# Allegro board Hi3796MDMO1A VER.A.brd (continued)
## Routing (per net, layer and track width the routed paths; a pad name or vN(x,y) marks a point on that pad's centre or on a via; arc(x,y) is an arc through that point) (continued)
STANDBY_PWROFF: length 225
  TOP w0.127: 36.96,68.45 37.54,67.87 45.59,67.87 46.86,69.14 v1(46.86,71.37) ; 36.96,68.45 36.42,67.92 24.23,67.92 23.37,67.06 18.36,67.06 12.19,60.88 12.19,57.58 13.84,55.93 v1(15.27,55.93) ; 36.96,68.45 R163.1 ; U10.AG27 v2(72.38,42.74) ; v1(35.31,13.84) 50.88,13.84 v1(53.34,16.31) 55.85,13.79 64.29,13.79 67.08,16.59 68.5,16.59 73.79,21.87 v1(73.79,28.83) ; v1(103.14,52.05) 101.96,53.24 101.96,55.78 100.91,56.82 100.91,57.33 100.46,57.79 99.67,57.79 R73.1
  BOTTOM w0.127: v1(103.14,52.05) 101.71,52.05 91.44,41.78 88.52,41.78 82.68,35.94 78.13,35.94 76.71,34.52 76.71,31.75 v1(73.79,28.83) R142.1 72.03,32.87 71.75,33.15 71.75,41.4 71.53,41.63 R88.1 71.92,42.22 71.92,42.28 v2(72.38,42.74) ; v1(35.31,13.84) 32.38,16.76 21.21,16.76 14.1,23.88 14.1,33.53 15.37,34.8 15.37,39.24 16,39.88 16,55.19 v1(15.27,55.93) ; v1(53.34,16.31) 53.37,16.33 R33.1 ; R30.1 47.09,71.6 v1(46.86,71.37)
TSI0_CLK: length 96.6
  TOP w0.127: J7.19 130.58,79.63 132.33,79.63 134.87,77.09 134.87,56.64 131.7,53.47 119,53.47 117.64,54.83 111.47,54.83 108.84,52.2 106.3,52.2 104.09,49.99 91.36,49.99 89.28,52.07 82.98,52.07 80.57,54.48 75.6,54.48 75.3,54.18 73.23,54.18 73.03,53.98 72.36,53.98 72,54.34 U10.N27
TSI0_D0: length 90.8
  TOP w0.127: U10.N28 73.18,54.74 73.79,54.74 74.3,55.25 81.29,55.25 83.76,52.77 90.03,52.77 91.82,50.98 103.63,50.98 105.89,53.24 108.86,53.24 111.43,55.8 119.2,55.8 120.27,54.74 131.19,54.74 133.86,57.4 133.86,75.82 132.33,77.34 130.32,77.34 J7.17
TSI0_VALID: length 98.1
  TOP w0.127: J7.21 128.14,82.28 128.14,77.85 129.03,76.96 132.21,76.96 133.48,75.69 133.48,57.53 130.94,54.99 120.37,54.99 119.31,56.06 111.22,56.06 108.73,53.57 105.84,53.57 103.58,51.31 91.87,51.31 90.16,53.02 83.87,53.02 81.39,55.5 74.04,55.5 73.68,55.14 U10.M26
TSI1_CLK: length 14.4
  TOP w0.127: R10.1 79.17,64.82 78.61,64.26 78.61,62.87 75.67,59.92 75.67,58.19 74.75,57.28 73.32,57.28 U10.K28
TSI1_D0: length 12.2
  TOP w0.127: R13.1 79.6,62.43 76.63,59.46 76.63,58.14 74.78,56.29 72.36,56.29 72.02,55.94 U10.L27
TSI1_SYNC: length 17.4
  TOP w0.127: U10.H26 74.03,58.34 74.42,58.72 74.42,61.47 74.46,61.51 74.46,61.51 75.28,62.33 76.05,62.33 77.47,63.75 77.47,65.91 78.64,67.08 80.42,67.08 80.64,66.85 R226.1
TSI1_VALID: length 17
  TOP w0.127: v1(79.63,66.55) 78.61,66.55 77.85,65.79 77.85,63.5 76.2,61.85 75.15,61.85 74.68,61.37 74.68,58.6 74.12,58.04 72.48,58.04 U10.J27
  TOP w0.381: R5.1 v1(81.28,65.84)
  BOTTOM w0.127: v1(79.63,66.55) 80.34,65.84 v1(81.28,65.84)
TX+_PHY0: length 38.4
  TOP w0.114: R80.1 33.3,83.69 34.29,83.69 35.56,82.42 39.88,82.42 40.5,83.05 41.29,83.05 41.4,82.93 U27.8 U27.1 43.18,82.93 43.3,83.06 44.76,83.06 45.95,81.87 51.55,76.27 51.55,66.49 53.71,64.33 53.71,63.95 53.96,63.69 53.96,61.95 U10.D5
TX-_PHY0: length 38.5
  TOP w0.114: R79.1 33.29,83.96 34.4,83.96 35.67,82.69 39.77,82.69 40.39,83.31 41.27,83.31 41.4,83.44 U27.7 U27.2 43.15,83.44 43.27,83.32 44.87,83.32 46.14,82.06 51.82,76.38 51.82,66.6 52.34,66.07 52.51,66.07 52.54,66.1 52.7,66.1 52.86,65.94 52.86,65.78 52.83,65.75 52.83,65.59 52.99,65.42 53.15,65.42 53.18,65.45 53.34,65.45 53.51,65.29 53.51,65.13 53.48,65.1 53.48,64.94 53.98,64.44 53.98,64.06 54.23,63.8 54.23,62.48 U10.C5
UART0_RXD: length 53.2
  TOP w0.127: v1(86.49,26.09) 86,26.09 79.25,32.84 79.25,33.78 74.78,38.25 74.78,42.49 73.33,43.94 U10.AF28 ; J18.2 66.95,12.09 67.94,13.08 R136.1 68.55,13.69 71.37,16.51 80.64,16.51 83.82,19.69 v1(83.82,20.07)
  BOTTOM w0.127: v1(86.49,26.09) 86.41,26.09 83.82,23.49 v1(83.82,20.07)
UART0_TXD: length 41.9
  TOP w0.127: v1(74.93,28.83) 74.24,28.14 74.24,21.67 68.58,16 67.51,16 67.31,15.8 67.31,13.84 67.16,13.69 R135.2 66.67,13.21 65.7,12.23 J18.3 ; U10.AF27 72.35,43.56 73.33,43.56 74.42,42.47 74.42,37.72 v1(77.85,34.29)
  BOTTOM w0.127: v1(77.85,34.29) 77.57,34.01 77.57,31.47 v1(74.93,28.83)
USB0_DM: length 58.1
  TOP w0.152: J6.2 9.98,66.38 12.38,66.38 D5.1 C341.2 14.05,66.37 14.68,66.37 17.21,68.9 21.4,68.9 v1(21.72,69.21) ; v1(56.22,69.24) 55.91,68.92 55.91,66.95 56.59,66.27 56.59,65.94 56.39,65.74 56.39,65.28 56.59,65.07 56.59,64.72 56.39,64.52 56.39,64.14 56.6,63.94 U10.A8
  BOTTOM w0.152: v1(21.72,69.21) 22.06,68.87 23.68,68.87 24.07,68.48 29.2,68.48 32.04,71.32 45.14,71.32 46.15,70.31 49.14,70.31 49.77,70.94 54.97,70.94 55.91,69.99 55.91,69.54 v1(56.22,69.24)
USB0_DP: length 58.1
  TOP w0.152: v1(55.29,69.24) 55.58,68.95 55.58,66.82 56.06,66.33 56.06,64.01 56.78,63.29 U10.B8 ; v1(21.72,68.28) 21.56,68.43 21.56,68.44 21.44,68.57 17.35,68.57 14.82,66.04 14.02,66.04 C342.2 D4.1 12.38,66.05 10.19,66.05 J6.3
  BOTTOM w0.152: v1(55.29,69.24) 55.58,69.53 55.58,69.86 54.83,70.61 49.91,70.61 49.28,69.98 46.01,69.98 45,70.99 32.18,70.99 29.34,68.15 23.93,68.15 23.55,68.54 21.98,68.54 v1(21.72,68.28)
USB01_1V1: length 4.3
  TOP w0.254: U10.H11 v2(58.78,58.74)
  BOTTOM w0.381: LB31.2 58.69,57.76 58.64,57.71 C336.1 C334.1 58.76,58.72 v2(58.78,58.74)
USB01_3V3: length 3.9
  TOP w0.254: U10.E10 v2(57.98,61.14)
  BOTTOM w0.381: v2(57.98,61.14) 58.62,61.78 C182.1 C10.1 59.77,62 60.36,62.6 LB20.2
USB1_DM: length 67.1
  TOP w0.152: v1(58.89,70.38) 58.59,70.08 58.59,65.57 58.35,65.34 58.35,65.01 58.09,64.74 57.76,64.74 57.48,64.47 57.48,64.19 57.68,63.98 57.68,63.65 57.48,63.45 57.48,62.43 U10.C9 ; J9.2 10.13,88.23 11.87,88.23 D10.1 C343.2 13.92,88.57 v1(14.02,88.47)
  BOTTOM w0.152: v1(58.89,70.38) 58.6,70.67 58.6,71.38 56.61,73.37 49.73,80.26 42.05,80.26 40.47,81.84 25.35,81.84 19,88.19 14.3,88.19 v1(14.02,88.47)
USB1_DP: length 67.2
  TOP w0.152: J9.3 10.03,87.9 11.77,87.9 D15.1 C344.2 13.94,87.45 v1(14.02,87.53) ; U10.D9 57.15,61.96 57.15,64.6 58.25,65.71 58.25,70.08 v1(57.95,70.38)
  BOTTOM w0.152: v1(57.95,70.38) 58.27,70.7 58.27,71.25 56.38,73.14 49.59,79.93 41.91,79.93 40.34,81.51 25.21,81.51 18.86,87.86 14.35,87.86 v1(14.02,87.53)
USB01_VBUS: length 0.9
  TOP w0.508: C49.1 12.95,68.58
  vias: v1(11.68,91.82) v1(11.68,90.68) v1(11.7,73.8) v1(11.7,72.66) v1(12.73,73.8)
USB2_DM: length 45.7
  TOP w0.152: U10.T27 72.35,51.56 73.06,51.56 73.14,51.64 80.1,51.64 81.98,49.76 87.62,49.76 90.67,46.71 104.84,46.71 106,47.88 111.25,47.88 111.53,47.6 112.17,47.6 113.01,46.75 U7.4
USB2_DP: length 45.7
  TOP w0.152: U7.3 113.13,48.75 112.3,47.93 111.67,47.93 111.39,48.21 105.87,48.21 104.7,47.04 90.81,47.04 87.76,50.09 82.12,50.09 80.06,52.15 79.76,52.15 79.58,51.97 79.15,51.97 78.92,52.2 78.62,52.2 78.39,51.97 77.96,51.97 77.73,52.2 77.4,52.2 77.17,51.97 76.74,51.97 76.57,52.15 76.13,52.15 75.96,51.97 75.27,51.97 75.12,52.12 74.66,52.12 74.51,51.97 74.05,51.97 73.9,52.12 73.44,52.12 73.29,51.97 73,51.97 72.92,51.89 72.82,51.89 U10.T28
USB2_RBI: length 2.6
  TOP w0.127: U10.R25 v2(70.78,52.34)
  BOTTOM w0.127: R85.1 R43.1 71.02,52.58 v2(70.78,52.34)
USB3_DM: length 86.1
  TOP w0.152: U10.AH19 65.53,42.29 65.53,41.11 65.13,40.71 65.13,40.43 65.28,40.27 65.41,40.27 65.56,40.12 65.56,39.82 65.41,39.66 65.28,39.66 65.13,39.51 65.13,39.21 65.28,39.06 65.41,39.06 65.56,38.9 65.56,38.6 65.41,38.45 65.28,38.45 65.13,38.29 65.13,38.03 54.24,27.15 31.68,27.15 25.73,33.11 25.73,39.55 15.32,49.96 10.97,49.96 8.64,47.62 8.64,46.88 8.84,46.68 8.84,46.3 8.64,46.1 8.64,45.82 8.86,45.59 8.86,45.31 8.64,45.09 8.64,44.48 8.94,44.17 9.09,44.17 J12.2
USB3_DP: length 86.1
  TOP w0.152: J12.3 9.3,43.84 8.8,43.84 8.31,44.34 8.31,47.76 10.83,50.29 15.46,50.29 26.06,39.69 26.06,33.24 31.82,27.48 54.11,27.48 64.8,38.17 64.8,40.84 65.2,41.25 65.2,42.76 U10.AG19
USB3_REXT: length 2.4
  TOP w0.127: U10.AD18 v2(65.18,45.14)
  BOTTOM w0.127: R55.1 66.18,44.78 66.14,44.74 65.57,44.74 v2(65.18,45.14)
USB3_RXN: length 77.9
  TOP w0.152: U10.AG21 67.56,42.75 67.56,42.42 68,41.98 68,37.75 54.91,24.66 31.01,24.66 23.47,32.21 23.47,37.58 20.11,40.94 12.36,40.94 J12.5
USB3_RXP: length 77.8
  TOP w0.152: J12.6 12.37,41.27 13.51,41.27 13.77,41.53 14.12,41.53 14.38,41.27 14.73,41.27 14.98,41.53 15.34,41.53 15.59,41.27 15.95,41.27 16.2,41.53 16.56,41.53 16.81,41.27 17.17,41.27 17.42,41.53 17.78,41.53 18.03,41.27 20.24,41.27 23.8,37.72 23.8,32.34 31.15,24.99 54.77,24.99 67.67,37.89 67.67,38.23 67.41,38.48 67.41,38.84 67.67,39.09 67.67,39.44 67.41,39.7 67.41,40.05 67.67,40.31 67.67,40.66 67.41,40.92 67.41,41.27 67.67,41.53 67.67,41.85 U10.AH21
USB3_TXN: length 75.5
  TOP w0.152: C129.2 16.03,46.99 16.38,46.99 24.58,38.79 24.58,32.63 26.46,30.75 31.36,25.85 54.56,25.85 66.75,38.04 66.75,44.36 U10.AE20
USB3_TXP: length 75.6
  TOP w0.152: C70.2 15.95,47.32 16.52,47.32 17.11,46.73 17.38,46.73 17.68,46.43 17.68,46.22 17.68,46.16 17.97,45.87 18.24,45.87 18.54,45.57 18.54,45.36 18.54,45.3 24.91,38.93 24.91,32.77 31.5,26.18 32.09,26.18 32.25,26.34 32.7,26.34 32.86,26.18 33.31,26.18 33.47,26.34 33.92,26.34 34.08,26.18 52.11,26.18 52.29,26.37 52.72,26.37 52.9,26.18 53.33,26.18 53.51,26.37 53.94,26.37 54.12,26.18 54.42,26.18 66.42,38.18 66.42,39.34 66.27,39.5 66.27,39.9 66.42,40.06 66.42,40.46 66.27,40.61 66.27,41.09 66.42,41.24 66.42,41.52 66.24,41.7 66.24,42.09 66.42,42.27 66.42,42.55 66.19,42.77 66.19,43.08 66.42,43.31 66.42,43.98 U10.AF20
USB_BOOT: length 11.3
  TOP w0.127: v1(75.18,70.1) 73.03,67.94 73.03,65.61 71.98,64.56 U10.A27
  BOTTOM w0.127: R40.2 76.71,71.63 v1(75.18,70.1)
USBRBIAS: length 2.2
  TOP w0.254: U10.G11 v2(58.78,59.54)
  BOTTOM w0.254: v2(58.78,59.54) 58.83,59.49 R87.2 R44.2
VDAC_3V3: length 1.1
  TOP w0.254: U10.F24 v2(69.98,60.34) ; U10.F23 v2(69.18,60.34)
VDAC_IREF: length 1.2
  TOP w0.127: U10.B24 v2(69.98,63.54)
  BOTTOM w0.127: R32.2 69.94,63.58 v2(69.98,63.54)
XIN: length 14.3
  TOP w0.203: X2.1 82.64,41.11 82.4,41.35 78.51,41.35 78.33,41.17 C364.1 77.7,40.82 R1.2 77.11,41.3 75.98,42.43 75.98,42.89 73.86,45.01 72.5,45.01 U10.AD27
XOUT: length 7.1
  TOP w0.203: R14.1 77.8,42.09 77.77,42.11 R1.1 76.43,42.9 76.43,43.13 74.02,45.54 U10.AD28
$4N759:
  vias: v1(22.48,98.81) v1(22.48,97.66) v1(23.62,98.81) v1(23.62,97.66)
$4N770: length 30.1
  TOP w0.127: R7.2 C43.1 101.37,53.61 v1(101.36,53.59)
  BOTTOM w0.127: R21.1 76.87,61.79 C71.1 78.85,61.79 85.85,54.79 95.96,54.79 97.03,53.72 101.23,53.72 v1(101.36,53.59)
$4N771: length 4.5
  TOP w0.381: U11.6 97.71,56.39 R99.2 R70.1 R53.1 C76.1
$4N777: length 1.1
  TOP w0.381: R7.1 R70.2
$4N778: length 2.6
  TOP w0.381: U11.1 97.9,58.6 C8.1 R73.2
$4N808: length 46.7
  TOP w0.127: v1(73.79,30.15) 73.15,29.51 73.15,27.05 72.77,26.67 71.88,26.67 71.6,26.39 C45.1 R49.2
  BOTTOM w0.127: C72.1 74.99,64.22 75.08,64.14 R23.1 75.72,62.92 75.72,61.44 77.09,60.07 78.36,60.07 80.01,58.42 80.01,45.67 78.28,43.94 78.28,42.88 74.93,39.52 74.93,31.29 v1(73.79,30.15)
$4N809: length 1
  TOP w0.381: R49.1 R17.2
$4N813: length 4
  TOP w0.381: v1(71.09,26.88) 70.57,26.88 70.14,26.45 U13.1
  BOTTOM w0.508: R142.2 C5.1 71.22,27 v1(71.09,26.88)
$4N877: length 3.9
  TOP w0.508: U15.5 34.92,70.91 R52.1 C84.1 R120.1
$4N879: length 3.4
  TOP w0.508: C30.1 R163.2 R6.2 37.97,71.42 U15.1
$4N1045: length 1.8
  TOP w0.508: U18.5 R95.2
$4N1055: length 8.2
  TOP w0.508: C178.2 29.84,71.75 29.59,72.01 v1(29.59,72.39)
  BOTTOM w0.508: v1(29.59,72.39) 29.59,73.05 30.48,73.94 30.48,75.95 29.84,76.58 v1(27.81,76.58)
$4N1066: length 1.8
  TOP w0.508: U18.6 28.64,71.39 R190.1
$4N1068: length 1
  TOP w0.508: R190.2 C178.1
$4N1073: length 1.8
  TOP w0.508: R172.1 26.67,71.88 26.74,71.95 U18.4
$4N1075: length 2.6
  TOP w0.508: R191.1 R105.1 25.45,70.38 R172.2
$4N1116: length 3.8
  TOP w0.381: U1.5 61.71,16.64 R131.1 C112.1 R100.1
$4N1127: length 2.5
  TOP w0.381: R48.2 C24.1 61.22,18.54 U1.1
$4N1138: length 5.3
  TOP w0.508: R47.1 71.58,22.99 71.58,22.43 70.99,21.84 70.99,20.45 ; R47.1 70.87,22.99 70.67,23.18 U13.6 ; R47.1 71.58,23.98 R17.1
$5N541: length 3.3
  TOP w0.508: Q4.3 52.07,20.62 v1(52.96,20.62)
  BOTTOM w0.508: v1(52.96,20.62) 52.55,20.22 R144.2 R118.2
$5N542: length 15
  TOP w0.381: v1(49.02,16.56) 48.39,16.56 Q8.1
  BOTTOM w0.381: R118.1 53.37,18.19 53.07,17.89 52.08,17.89 51.45,18.53 C6.2 51.05,17.65 49.96,16.56 v1(49.02,16.56) 49.02,18.21 48.03,19.2 46.71,19.2 46.1,19.81 Q13.1
$5N591: length 4.7
  TOP w0.508: Q3.1 45.85,76.5 v1(44.96,75.62)
  BOTTOM w0.508: C133.2 44.69,75.88 v1(44.96,75.62) 44.98,75.59 R75.1
$5N592: length 4.1
  TOP w0.508: v1(46.1,72.06) 46.61,72.57 Q9.3
  BOTTOM w0.508: R75.2 46.2,74.5 R98.2 46.1,73.56 v1(46.1,72.06)
$5N601: length 3.2
  TOP w0.508: Q4.1 50.93,16.81 v1(51.05,16.69)
  BOTTOM w0.508: R33.2 51.38,17.02 v1(51.05,16.69)
$5N603: length 2.3
  TOP w0.508: v1(48.26,71.3) 48.51,71.55 Q9.1
  BOTTOM w0.508: R30.2 47.9,71.65 v1(48.26,71.3)
$6N188: length 3.1
  TOP w0.203: X2.3 80.13,42.48 79.5,43.1 C365.1 R14.2
$6N2484: length 6.3
  TOP w0.127: R16.2 47.88,64.64 47.88,63.81 50.95,60.74 U10.E1
$7N2063: length 13.9
  BOTTOM w0.127: R40.1 C146.1 77.85,74.68 78.18,75 S10.1 79.45,76.78 80.39,77.72 80.39,82.68 80.08,82.98 S10.2
$8N1731: length 1.3
  TOP w0.127: U10.AC17 v2(64.38,45.94)
  BOTTOM w0.127: v2(64.38,45.94) 64.39,45.92 R45.1
$8N1816: length 5.7
  TOP w0.114: R36.2 56.37,39.25 56.71,39.58 56.71,40.89 56.38,41.22 56.38,43.32 56.78,43.73 56.78,43.93 U10.AF8
$8N1817: length 5.2
  TOP w0.114: U10.AG8 56.64,43 56.64,42.53 56.85,42.33 56.85,42.05 56.64,41.84 56.64,41.33 56.97,41 56.97,39.47 56.52,39.02 R37.2
$11N894: length 2.2
  TOP w0.127: U3.L8 v2(36.59,55.84)
  BOTTOM w0.127: R46.2 36.19,57.3 36.19,56.48 36.32,56.35 36.41,56.26 36.59,56.08 v2(36.59,55.84)
$12N1176: length 1.2
  TOP w0.127: U6.L8 v2(37.39,39.43)
  BOTTOM w0.127: R71.2 37.39,39.98 v2(37.39,39.43)
$13N604: length 3.2
  TOP w0.089: U22.K2 98.84,30.45 98.84,29.79
  TOP w0.127: v2(98.84,29.77) 98.84,29.79
  BOTTOM w0.127: C123.1 C124.1 99.22,29.39 v2(98.84,29.77)
$13N821: length 3
  TOP w0.127: U19.38 90.23,32.7 89.97,32.44 R25.2
$14N447: length 2
  TOP w0.508: R220.1 13.31,79.35 13.72,79.76 U26.3
$14N448: length 1.6
  TOP w0.508: U26.4 12.83,77.44 12.83,77.44 R106.2
$14N520: length 2.1
  TOP w0.381: U16.3 22.8,47.83 23.01,47.62 R113.1
$14N521: length 1.5
  TOP w0.508: R115.2 22.45,51.94 22.79,51.6 22.79,51.02 U16.4
$14N652: length 3.8
  TOP w0.152: J12.9 12.36,47.28 14.49,47.28 C70.1
$14N653: length 3.8
  TOP w0.152: C129.1 14.49,46.95 12.37,46.95 J12.8
$14N657: length 0.9
  TOP w0.508: C52.1 11.4,54.71 v1(11.43,54.74)
  vias: v1(12.7,54.74)
$15N771: length 7.3
  TOP w0.508: R178.2 76.19,13.94 C181.1 74.82,13.96 C177.1 74.8,13.06 77.06,10.79 D3.3
$15N777: length 4.1
  TOP w0.508: R77.2 R175.1 22.48,18.62 C157.2 22.48,21.21 Q15.1
$15N781: length 7.9
  TOP w0.381: Q5.1 19.74,13.49 19.35,13.87 19.35,15.11 18.77,15.7 R76.2
$15N783: length 5
  TOP w0.508: Q5.3 20.42,15.34 19.91,15.85 19.91,18.11 20.37,18.57 R175.2
$15N894: length 11.1
  TOP w0.254: R34.2 83.38,16.89 82.73,16.24 82.73,13.13 Q2.3 79.96,10.36 LED1.1
$15N896: length 8.2
  TOP w0.254: R129.2 86.56,16.33 86.49,16.26 Q7.3 86.49,10.8 LED1.3
$15N901: length 1.6
  TOP w0.254: Q7.1 87.5,16.26 87.63,16.38 R22.2
$15N1018: length 6.6
  TOP w0.127: R31.2 88.42,14.1 v1(88.01,14.1) ; 83.69,15.37 83.69,14.73 v1(84.2,14.22)
  BOTTOM w0.127: v1(88.01,14.1) 87.5,14.61 84.58,14.61 v1(84.2,14.22)
$16N873: length 5.5
  TOP w0.356: U5.5 65.22,91.4 65.2,91.41 C363.1
  TOP w0.381: 64.54,92.63 R90.2 R229.1 ; 64.54,92.63 64.54,91.45 C363.1 ; 64.54,92.63 R139.1
$16N884: length 2.5
  TOP w0.356: U5.7 v1(67.61,90.1)
  BOTTOM w0.381: v1(67.61,90.1) 67.67,90.04 C32.1
$16N889: length 2.1
  TOP w0.356: U5.6 65.55,90.75 65.07,90.27 C33.2
$16N895: length 2.6
  TOP w0.356: U5.8 v1(71.17,90.1)
  BOTTOM w0.381: v1(71.17,90.1) 71.12,90.04 C32.2
$16N1022: length 1.3
  TOP w0.381: C351.2 66.92,83.07 R193.1
$16N1024: length 3.6
  TOP w0.254: R193.2 C317.1 R27.1 66.63,85.52 R19.1
$16N1034: length 13.8
  TOP w0.254: R74.2 R146.1 66.19,95.65 65.28,94.74 65.28,92.84 65.41,92.71 66.46,92.71 U5.3 67.73,92.7 68.25,92.17 68.25,89.84 67.14,88.73 C55.2 67.14,87.51 R19.2
$16N1035: length 8.5
  TOP w0.254: R27.2 68,88 C55.1 67.96,88.78 68.83,89.66 68.83,92.35 67.84,93.35 U5.2
$16N1048: length 15.5
  TOP w0.254: R119.1 R145.1 70.84,95.65 71.88,94.61 73.1,94.61 73.41,94.31 73.41,92.96 73.14,92.7 U5.12 71.19,92.7 70.43,91.94 70.43,88.42 C54.1 70.69,87.65 R97.1
$16N1049: length 1.5
  TOP w0.254: C350.1 70.85,82.69 R194.2
$16N1050: length 3.7
  TOP w0.254: R97.2 70.79,85.52 70.79,85.52 R28.2 C316.1 R194.1
$16N1054: length 8.5
  TOP w0.254: U5.13 70.82,93.35 69.9,92.43 69.9,89.33 69.37,88.8 C54.2 69.37,87.55 69.39,87.53 R28.1
$16N1079: length 2
  TOP w0.305: R93.1 73.53,92.25 73.33,92.05 U5.11
$16N1086: length 2
  TOP w0.381: R94.1 R174.2 R93.2
$17N163:
  vias: v1(36.22,87.99) v1(37.01,87.96)
$17N165: length 10
  TOP w0.406: J25.9 25.37,97.81 25.37,89.82 R67.1
$17N170: length 15.6
  TOP w0.406: R185.1 42.64,89.16 42.64,97.77 40.63,99.78 38.77,99.78 J25.11
$17N171: length 13.4
  BOTTOM w0.508: J25.7 35.87,104.83 35.87,104.07 J25.8 36.54,101.31 35.65,100.42 35.65,97.86 R182.2
$17N172: length 3.8
  TOP w0.508: T2.15 v1(30.22,93.99)
  BOTTOM w0.508: v1(30.22,93.99) 30.97,93.99 31.13,94.15 R181.2
$17N173: length 2.7
  TOP w0.508: T2.10 36.57,94.1 v1(36.35,93.88)
  BOTTOM w0.508: R180.2 36.61,94.15 v1(36.35,93.88)
$17N175: length 11.7
  TOP w0.254: T2.9 37.84,96.61 37.6,96.85 36.73,96.85 36.24,97.34 32.69,100.89 32.69,102.01 33.03,102.34 33.46,102.34 J25.6
$17N176: length 11.8
  TOP w0.254: T2.11 35.3,96.4 35.73,96.83 35.73,97.27 32.28,100.72 32.28,101.95 31.46,102.77 J25.3
$17N177: length 10
  BOTTOM w0.635: R181.1 32.73,92.38 R272.1 35.24,92.29 R180.1 R182.1 40.48,92.29 C23.1
$17N178: length 12
  TOP w0.254: J25.1 29.43,104.58 28.64,103.79 28.64,101.26 30.55,99.36 30.55,97.76 30.06,97.28 30.06,96.86 29.84,96.63 29.18,96.63 28.95,96.4 T2.16
$17N179: length 11.9
  TOP w0.254: T2.14 31.49,96.37 31.26,96.6 30.67,96.6 30.47,96.81 30.47,97.11 30.95,97.59 30.95,99.53 29.05,101.43 29.05,103.62 29.52,104.09 29.75,104.09 J25.2
$17N180: length 12.5
  BOTTOM w0.508: R272.2 32.48,96.9 J25.4 32.48,104.16 J25.5
$17N184:
  vias: v1(29.87,87.93) v1(30.68,87.91)
$17N276: length 5.5
  TOP w0.114: R80.2 31.73,83.69 30.18,83.69 29.87,84 29.87,85.06 28.95,85.99 T2.1
$17N279: length 5.5
  TOP w0.114: R79.2 31.73,83.95 30.29,83.95 30.14,84.11 30.14,84.99 30.26,85.12 30.71,85.12 31.49,85.89 T2.3
$17N281: length 4.4
  TOP w0.114: R50.2 37.06,83.69 36.6,83.69 36.18,84.11 36.18,85.09 35.3,85.97 T2.6
$17N285: length 4.4
  TOP w0.114: T2.8 37.84,85.92 37.16,85.24 36.7,85.24 36.45,84.99 36.45,84.22 36.71,83.96 37.07,83.96 R18.2
$19N506: length 2.4
  TOP w0.127: D12.1 55.24,90.73 55.21,90.76 R184.1
$20N275: length 4
  TOP w0.127: R127.1 R69.2 84.69,70.32 U2.37
$20N304: length 2.3
  TOP w0.203: C226.1 92.05,71.04 91.49,71.04 90.77,70.32 U2.24
$20N444: length 7.8
  TOP w0.508: U12.4 80.92,82.78 80.39,83.31 R68.2
  vias: v1(84.33,79.38) v1(84.33,78.49) v1(85.22,79.38) v1(93.47,76) v1(94.36,75.95)
$20N446: length 3.7
  TOP w0.508: R68.1 R141.1 75.03,82.14 U12.1
$21N322: length 3.8
  TOP w0.203: U34.27 112.78,93.71 C487.2 112.97,93.31 U34.26
$21N324: length 3.1
  TOP w0.203: U34.24 111.93,92.51 112.43,92.01 112.43,91.31 C168.2
$21N325: length 9.3
  TOP w0.203: U34.20 110.08,89.11 110.58,88.61 C190.1 110.65,89.73 110.48,89.9 U34.21 ; 111.25,91.41 U34.22
  TOP w0.254: C194.1 111.67,89.35 111.25,89.76 111.25,91.41
  TOP w0.381: C190.1 C194.1
$21N326: length 7.7
  TOP w0.127: U34.15 108.08,90.58 107.24,89.75 106.35,89.75 105.32,88.71 105.32,88.43 C538.1 104.83,88.3 104.55,88.58 103.32,88.58 R61.1
$21N327: length 9.2
  TOP w0.127: R62.1 103.32,87.31 104.55,87.31 104.83,87.03 C534.1 105.57,87.41 105.57,88.58 106.46,89.47 107.47,89.47 108.48,90.48 U34.16
$21N328: length 3.1
  TOP w0.127: U34.17 108.88,90.44 R72.1
$21N329: length 12
  TOP w0.203: C532.1 108.24,89.02 109.28,90.06 U34.18
  TOP w0.254: C532.1 108.24,88.58 107.73,88.58 107.6,88.46 107.6,84.14 106.33,82.87 X4.1
$21N330: length 12.2
  TOP w0.203: U34.19 109.68,89.9 109.25,89.47 C531.1
  TOP w0.254: X4.2 110.27,82.87 109.89,83.25 109.89,88.46 109.73,88.61 C531.1
$21N331: length 3.9
  TOP w0.127: U34.14 107.3,91.08 105.44,89.22 R59.1
$21N332: length 6.4
  TOP w0.127: U34.13 106.81,92.11 106.59,91.89 106.59,90.87 105.7,89.98 103.44,89.98 R64.1
$21N333: length 6.4
  TOP w0.114: U34.12 106.69,92.51 106.2,92.01 105.98,91.8 105.98,91.35 105.71,91.08 105.43,91.08 C537.1 104.83,90.71 104.46,91.08 103.27,91.08 C303.1
$21N334: length 6.3
  TOP w0.114: U34.11 106.86,92.91 106.82,92.86 106.67,92.86 106.26,92.45 106.01,92.2 106.01,92.2 105.72,91.91 105.72,91.47 105.6,91.35 105.35,91.35 104.83,91.87 ; 104.83,91.87 104.83,91.72 104.46,91.35 103.21,91.35 C307.1 ; 104.83,91.87 C241.1
$21N336: length 5.5
  TOP w0.114: C186.1 103.27,93.88 104.46,93.88 104.83,93.51 C535.1 105.32,93.77 106.52,93.77 106.58,93.71 U34.9
$21N337: length 5.5
  TOP w0.114: U34.8 106.58,94.11 106.52,94.04 105.51,94.04 C536.1 104.87,94.55 104.46,94.15 103.12,94.15 C306.1
$21N338: length 5
  TOP w0.203: 109.68,96.21 U34.3
  TOP w0.508: L1.2 R63.1 109.68,96.21
$21N360: length 1.1
  TOP w0.508: C304.2 R63.2
$21N368: length 2.9
  TOP w0.508: L1.1 C305.2 113.67,99.6 C64.2
$21N406: length 4.8
  TOP w0.127: C148.1 108.21,98.24 108.21,96.85 108.66,96.39 108.84,96.39 109.28,95.95 U34.4
$21N416: length 8.1
  TOP w0.127: v1(107.93,95.95) 107.98,95.95 108.48,95.45 U34.6 ; R60.2 102.85,95.83 103.36,96.33 104.68,96.33 104.87,96.14 C545.1 105.39,95.7 v1(106.11,94.98)
  BOTTOM w0.127: v1(107.93,95.95) 107.07,95.95 v1(106.11,94.98)
$21N439: length 3.6
  TOP w0.508: U14.1 v1(137.06,95.1)
  BOTTOM w0.508: R112.1 134.82,94.97 R2.1 136.93,94.97 v1(137.06,95.1)
$21N597: length 4.6
  TOP w0.508: C283.2 L16.2 C282.1
$21N600: length 4.9
  TOP w0.203: 107.35,95.19 107.98,95.19 108.08,95.09 U34.7
  TOP w0.508: 107.35,95.19 106.47,96.07 arc(105.92,96.89) 105.72,97.86 C282.2
$21N629:
  vias: v1(129.29,96.01) v1(130.05,96.01)
$21N809: length 3.3
  TOP w0.305: U17.2 114.31,60.8 C171.2
$21N822: length 3.8
  TOP w0.305: U17.4 115.61,60.75 115.84,60.51 C175.2 116.73,59.68 C163.2
$21N827: length 1
  TOP w0.381: R102.2 115.03,58.67 C175.1
$21N836: length 3.3
  TOP w0.305: U17.6 116.91,61.15 118.23,59.83 R117.2
$21N838: length 3.4
  TOP w0.305: R121.2 119.12,59.73 117.56,61.29 U17.7
$21N849: length 2.6
  TOP w0.356: U17.14 114.96,69.55 114.27,70.23 C139.1
$21N880: length 2.8
  BOTTOM w0.508: C151.1 117.09,69.6 v1(116.71,69.98) 116.64,70.05 C244.1
$21N898: length 2.8
  TOP w0.305: U17.11 116.91,69.16 118.07,70.32 R92.1
$21N900: length 3.6
  TOP w0.305: U17.10 117.56,69.17 118.13,69.74 119.02,69.74 119.34,70.06 C246.1
$21N922: length 5.5
  TOP w0.508: Q6.1 123.7,80.9 122.81,81.79 122.81,83.14 R51.2 123.73,85.34 R114.1
$21N925: length 2.6
  TOP w0.508: C155.1 123.7,87.66 R114.2 R35.2
$22N979: length 8.6
  TOP w0.127: R125.1 C490.1 R126.2 ; R39.2 R126.2 ; R126.2 118.87,13.84 119.03,13.69 J1.6
$22N990: length 6.6
  TOP w0.508: Q1.2 112.39,19.81 114.17,21.59 LB33.2 115.21,21.19 116.18,20.22 R20.1
$22N994: length 3.9
  TOP w0.508: R302.1 110.41,17.32 110.62,17.53 112.83,17.53 Q1.3
$22N995: length 3.8
  TOP w0.508: R242.2 R20.2 114.6,19.41 Q1.1
$22N1000: length 2.7
  TOP w0.127: U24.9 128.41,29 v1(128.4,29.01)
  BOTTOM w0.127: R168.2 v1(128.4,29.01)
$22N1006: length 6.2
  TOP w0.127: 123.2,26.09 123.2,27.35 U24.13 ; 123.2,26.09 v1(123.19,26.09) ; 123.2,26.09 123.25,26.03 125.09,26.03 125.87,26.81 U24.11
  BOTTOM w0.127: R270.1 123.32,26.21 v1(123.19,26.09)
$22N1011: length 4.3
  BOTTOM w0.127: R38.2 124.59,24.28 124.82,24.51 R267.2 124.82,26.82 Q14.2

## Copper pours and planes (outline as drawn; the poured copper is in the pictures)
1V1_CORE on TOP (solid shape): 72.01,32.77 72.01,30.35 71.95,30.29 68.24,30.29 68,30.05 68,29.72 67.74,29.46 65.2,29.46 65.18,29.49 65.18,32.61 65.58,33.02 71.75,33.02
1V1_CORE on BOTTOM (solid shape): 69.09,32.89 69.09,30.23 68.96,30.1 65.53,30.1 65.41,30.23 65.41,30.61 67.94,33.15 68.83,33.15
1V1_CORE on TOP: outline of 95 points within 58.55,49.71 64.64,57.45
1V1_CORE on BOTTOM: 63.17,48.01 63.12,48.06 63.12,48.44 62.23,49.33 61.47,49.33 61.21,49.58 58.72,49.58 58.55,49.76 58.55,53.52 58.67,53.64 59.18,53.64 59.31,53.52 59.31,52.88 59.05,52.63 59.05,51.36 59.18,51.23 61.59,51.23 61.72,51.36 61.72,51.99 61.59,52.12 61.09,52.12 60.96,52.25 60.96,52.63 61.09,52.76 61.34,52.76 61.47,52.88 61.47,53.52 61.34,53.64 61.09,53.64 60.96,53.77 60.96,54.03 61.09,54.15 61.47,54.15 61.59,54.28 61.59,55.04 61.47,55.17 60.83,55.17 60.71,55.3 60.71,57.33 60.58,57.45 60.58,57.96 60.71,58.09 61.09,58.09 61.34,57.84 61.34,57.43 61.44,57.33 64.64,57.33 64.77,57.2 65.41,57.2 65.53,57.07 65.53,56.82 65.41,56.69 63.37,56.69 63.25,56.57 63.25,50.47 63.37,50.34 63.75,50.34 63.88,50.22 63.88,49.96 63.37,49.45 63.37,48.95 63.55,48.77 63.5,48.77 63.5,48.01 ; 10 cut-outs
1V1_CORE on POWER03: 65.91,37.74 65.91,43.03 65.79,43.16 65.79,44.63 61.52,48.9 58.73,48.9 58.42,49.2 58.42,55.04 58.35,55.12 58.42,55.19 58.42,56.72 59.23,57.53 64.34,57.53 64.64,57.22 64.64,53.54 64.84,53.34 65.73,53.34 69.16,49.91 69.16,47.27 69.6,46.84 73.18,46.84 74.04,45.97 74.04,32.74 71.27,29.97 61.32,29.97 60.44,30.85 60.44,32.27
1V1_CPU on TOP: 90.3,59.69 90.3,56.01 90.17,55.88 89.28,55.88 89.03,55.63 89.03,54.36 88.9,54.23 83.69,54.23 81.53,56.39 76.83,56.39 76.71,56.52 76.71,59.69 77.22,60.2 81.79,60.2 84.07,57.91 86.49,57.91 88.39,59.82 90.17,59.82 ; 2 cut-outs
1V1_CPU on TOP: 67.82,56.29 67.61,56.08 67.61,55.83 67.87,55.58 68.1,55.58 68.33,55.8 68.43,55.8 68.61,55.63 68.61,53.8 67.77,52.96 67.64,52.83 67.64,52.58 67.82,52.4 67.82,52.25 67.69,52.12 65.91,52.12 64.59,53.44 64.59,53.64 64.77,53.82 64.77,54.08 64.57,54.28 64.57,54.46 64.61,54.5 64.65,54.54 65.37,55.26 65.41,55.3 65.45,55.34 66.17,56.06 66.21,56.1 66.25,56.14 66.55,56.44 67.11,56.44 67.18,56.43 67.31,56.44 67.44,56.57 67.69,56.57 67.82,56.44
1V1_CPU on BOTTOM: 66.55,56.44 67.31,56.44 67.44,56.57 67.69,56.57 67.94,56.31 67.94,55.93 68.07,55.8 68.45,55.8 68.73,55.52 69.47,55.52 69.6,55.4 69.6,53.64 69.47,53.52 67.69,53.52 67.61,53.44 67.61,52.71 67.94,52.37 67.94,51.7 67.79,51.55 67.25,51.55 67.18,51.61 67.18,52.12 67.06,52.25 66.36,52.25 66.01,52.6 66.01,53.55 65.81,53.75 65,53.75 64.9,53.86 64.9,54.91 65.02,55.04 65.49,55.04 65.61,55.16 65.61,55.69 65.72,55.8 66.17,55.8 66.42,56.06 66.42,56.31 ; 5 cut-outs
1V1_CPU on BOTTOM: 86.21,58.8 87.76,58.8 87.88,58.67 87.88,57.53 87.76,57.4 86.85,57.4 86.11,58.14 86.11,58.7
1V1_CPU on POWER03: 65.84,53.59 64.95,53.59 64.9,53.65 64.9,56.77 70.76,56.77 70.89,56.64 71.1,56.64 74.03,59.57 78.12,59.57 78.49,59.21 78.49,52.96 75.29,49.76 69.67,49.76 ; 1 cut-out
1V2_DVDD_S on TOP: 91.69,73.2 94.36,73.2 94.49,73.08 94.49,72.31 94.11,71.93 92.96,71.93 92.58,71.55 91.54,71.55 90.96,70.97 90.78,70.97 90.58,71.16 90.58,71.66 91.57,72.64 91.57,73.08
1V5_DDR3 on TOP: 43.18,71.25 43.18,75.06 43.31,75.18 45.72,75.18 45.85,75.06 45.85,68.96 45.15,68.26 42.48,68.26 42.42,68.33 42.42,70.48
1V5_DDR3 on TOP: outline of 137 points within 52.96,44.12 62.99,55.04
1V5_DDR3 on BOTTOM: 53.77,42.47 53.62,42.62 53.62,43.28 52.73,43.28 52.6,43.41 52.6,44.11 52.83,44.34 52.83,45.14 53.85,46.15 54.36,46.15 54.61,46.41 54.61,46.91 54.74,47.04 54.99,47.04 55.24,47.29 55.24,54.91 55.5,55.17 57.28,55.17 57.4,55.04 57.4,53.9 57.28,53.77 56.77,53.77 56.64,53.64 56.64,52.25 56.13,51.74 56.13,50.22 56.9,49.45 57.15,49.45 57.4,49.2 57.4,48.14 56.59,48.14 56.48,48.03 56.48,47.18 56.62,47.04 58.42,47.04 58.55,47.17 58.55,48.44 58.67,48.56 59.69,48.56 59.82,48.44 59.82,47.29 60.07,47.04 62.87,47.04 62.99,46.91 62.99,46.53 62.87,46.41 60.33,46.41 59.94,46.02 59.94,45.77 59.82,45.64 59.44,45.64 59.31,45.77 59.31,46.02 58.93,46.41 57.02,46.41 56.77,46.15 56.77,45.77 56.64,45.64 56.29,45.64 56.29,45.67 55.82,45.67 55.82,44.95 55.75,44.88 54.74,44.88 54.36,44.5 54.36,44.25 54.74,43.87 54.74,42.6 54.61,42.47 ; 14 cut-outs
1V5_DDR3 on BOTTOM: 40.21,57.52 40.21,58.94 40.51,59.25 41.48,59.25 41.55,59.17 41.55,57.48 41.5,57.43 41.5,56.87 41.15,56.52 40.64,56.52 40.39,56.77 40.39,57.32 40.22,57.48
1V5_DDR3 on BOTTOM: 39.7,39.99 39.57,40.11 39.57,40.64 39.65,40.81 39.62,41 39.62,42.38 39.68,42.43 41.01,42.43 41.39,42.04 41.39,41.97 41.23,41.8 41.23,40.49 40.72,39.99
1V5_DDR3 on POWER03: 48.44,39.37 50.2,41.13 51.4,41.13 52.26,42 52.26,43.19 52.96,43.89 52.96,45.03 55.24,47.32 55.24,54.89 55.35,54.99 58.11,54.99 58.17,54.94 58.17,49.1 58.62,48.64 61.42,48.64 65.53,44.52 65.53,43.16 65.41,43.03 65.41,37.95 53.11,25.65 35.54,25.65 25.02,36.17 25.02,65.92 25.4,66.29 29.57,66.29 29.58,66.3 35.93,66.3 39.09,69.47 39.98,69.47 40.62,70.1 44.85,70.1 45.09,69.87 45.09,67.67 41.4,63.99 41.4,63.78 41.53,63.65 41.53,63.36 41.18,63.01 41.18,61.56 41.1,61.47 41.1,61.47 39.88,60.25 39.88,59.26 40.08,59.05 41.27,59.05 41.53,58.8 41.53,55.57 41.86,55.25 41.86,55.25 41.86,55.09 42.31,55.09 42.31,55 43.57,55 43.57,55.25 45.29,55.25 45.47,55.07 45.47,50.09 41.27,45.9 41.27,45.26 40.21,44.2 39.79,44.2 39.36,43.77 39.36,43.11 40.97,41.5 40.97,39.92 41.84,39.05 44.07,39.05 44.4,39.37
3V3 on TOP (solid shape): 62.96,25.26 62.96,23.04 62.84,22.92 58.97,22.92 58.72,22.68 58.72,22.35 58.47,22.1 56.13,22.1 55.88,22.35 55.88,23.47 57.81,25.4 62.81,25.4
3V3 on BOTTOM: 59,22.48 58.62,22.1 57.15,22.1 56.01,20.95 50.77,20.95 49.48,19.66 47.88,19.66 47.73,19.81 47.73,22.53 48.06,22.86 55.37,22.86 68.71,36.2 68.71,43.05 68.96,43.31 68.96,45.21 69.22,45.47 70.1,45.47 70.36,45.21 70.36,43.31 70.23,43.18 70.23,41.27 70.36,41.15 70.36,36.07 63.75,29.46 63.75,21.97 64.77,20.95 66.93,20.95 68.45,19.43 68.45,14.99 68.07,14.61 66.55,14.61 66.17,14.99 66.17,17.04 64.41,18.8 63.75,18.8 60.07,22.48 ; 1 cut-out
3V3_DVDD_S on BOTTOM: 90.3,63.17 90.3,62.15 89.89,61.75 85.62,61.75 84.07,63.3 84.07,66.22 83.82,66.47 79.5,66.47 79.25,66.73 79.25,67.87 79.5,68.12 80.52,68.12 80.64,68 80.64,67.74 80.9,67.49 84.33,67.49 85.03,66.79 85.03,63.61 85.34,63.3 86.74,63.3 86.87,63.42 90.04,63.42
3V3_MOS on TOP: 127.76,85.45 127.76,82.79 127.39,82.42 125.86,82.42 125.73,82.55 125.73,85.47 125.75,85.49 127.72,85.49
3V3_MOS on TOP: 69.51,46.88 69.34,47.04 69.34,48.82 69.47,48.95 69.67,48.95 69.69,48.94 69.71,48.93 69.77,48.87 69.84,48.83 70.21,48.46 70.21,47.68 70.22,47.66 70.23,47.64 70.23,47.29 69.81,46.88
3V3_MOS on TOP: 73.03,77.47 75.18,77.47 75.44,77.22 75.44,76.17 75.75,75.85 75.75,74.62 75.68,74.55 74.55,74.55 74.3,74.3 73.03,74.3 72.9,74.42 72.9,77.34 ; 1 cut-out
3V3_MOS on TOP: 60.68,60.5 60.12,61.06 60.12,61.19 60.33,61.39 60.45,61.39 60.58,61.26 60.64,61.26 60.65,61.26 60.78,61.23 60.9,61.26 60.92,61.26 60.96,61.26 61.09,61.39 61.21,61.39 61.8,60.81 61.8,60.66 61.65,60.5
3V3_MOS on TOP: 108.71,46.61 108.84,46.48 108.84,45.06 108.74,44.96 107.19,44.96 107.06,45.09 107.06,46.46 107.21,46.61
3V3_MOS on TOP: 69.34,55.68 69.22,55.8 69.22,56.69 68.83,57.07 68.83,57.96 69.85,58.98 70.1,58.98 70.23,58.85 70.23,58.65 70.05,58.47 69.98,58.47 69.22,57.71 69.22,57.45 69.47,57.2 69.72,57.2 69.85,57.33 70.1,57.33 70.23,57.2 70.23,57.07 70.1,56.95 70.1,56.88 70.1,56.87 70.07,56.74 70.1,56.61 70.1,56.6 70.1,56.57 70.23,56.44 70.23,56.31 69.6,55.68
3V3_MOS on TOP: 124.21,37.47 128.4,37.47 128.78,37.08 128.78,35.56 128.27,35.05 124.33,35.05 124.08,35.31 124.08,37.34
3V3_MOS on BOTTOM: 48.01,18.67 48.51,18.16 48.51,16.64 48.9,16.26 50.67,16.26 50.8,16.13 50.8,14.35 50.67,14.22 46.35,14.22 45.34,15.24 45.34,18.54 45.47,18.67
3V3_MOS on BOTTOM: 68.13,48.82 68.71,48.82 68.83,48.95 68.83,49.71 68.96,49.83 69.47,49.83 69.6,49.71 69.6,48.77 69.72,48.64 71.04,48.64 71.12,48.56 71.12,47.19 70.99,47.07 70.51,47.07 70.46,47.02 69.24,47.02 69.22,47.04 68.96,47.04 68.83,47.17 68.83,47.55 68.71,47.68 68.16,47.68 68.1,47.73 68.1,48.79 ; 5 cut-outs
3V3_MOS on BOTTOM: 65.41,60.15 65.41,60.63 65.74,60.96 65.74,61.34 66.24,61.85 66.24,61.95 66.29,62 66.85,62 66.9,61.95 66.9,61.57 66.78,61.44 66.65,61.44 66.55,61.34 66.55,61.09 66.85,60.78 66.85,60.3 66.83,60.27 66.29,60.27 66.14,60.12 65.43,60.12 ; 2 cut-outs
3V3_MOS on BOTTOM: 119.02,65.71 120.52,65.71 120.62,65.61 120.62,64.24 120.6,64.21 118.95,64.21 118.75,64.41 118.75,65.43
3V3_MOS on BOTTOM: 79.06,68.78 78.99,68.71 78.99,67.82 78.87,67.69 78.49,67.69 78.36,67.82 78.36,70.52 79.49,71.66 79.49,72.24 79.61,72.35 80.48,72.35 80.6,72.23 80.6,70.93 80.66,70.88 80.66,68.93 80.51,68.78
3V3_MOS on POWER03: outline of 109 points within 16.26,11.56 130.68,89.41 ; 4 cut-outs
3V3_MOS_FLASH on TOP: 124.21,33.53 123.57,34.16 117.6,34.16 117.35,33.91 117.35,29.97 117.6,29.72 121.16,29.72 121.96,30.52 128.73,30.52 128.9,30.69 128.9,33.44 128.82,33.53
3V3_MOS_FLASH on POWER03: 86.61,28.42 86.61,38.48 88.77,40.64 119.4,40.64 120.27,39.77 120.27,37.22 120.26,37.13 120.27,37.12 120.27,30.84 117.5,28.07 86.97,28.07
3V3_RF on TOP: 132.86,91.96 133.1,92.2 133.1,96.27 133.22,96.39 134.24,96.39 134.37,96.27 134.37,91.31 135.38,90.3 135.38,87.76 135.25,87.63 132.08,87.63 131.95,87.76 131.95,88.39 131.7,88.65 128.66,88.65 128.66,88.64 128.02,88 128.02,86.99 127.57,86.53 126.07,86.53 125.86,86.74 125.86,87.34 125.36,87.84 125.36,87.97 125.35,87.98 125.35,88.39 124.97,88.77 124.97,91.48 125.45,91.96 ; 4 cut-outs
3V3_WIFI on TOP (solid shape): 110.87,46.48 110.87,45.85 111.12,45.59 115.19,45.59 115.57,45.21 115.57,44.2 115.19,43.82 112.27,43.82 110.96,42.5 110.15,42.5 110.11,42.55 110.11,43.18 109.73,43.56 109.73,46.48 109.86,46.61 110.74,46.61
5V0 on TOP (solid shape): 58.11,16.45 59.26,16.45 59.28,16.43 59.28,14.86 58.87,14.45 55.72,14.45 55.35,14.82 55.35,15.88 58.01,15.88 58.01,16.26 57.76,16.26 57.76,15.88 55.35,15.88 55.35,16.56 55.4,16.62 57.95,16.62
5V0 on TOP (solid shape): 67.37,23.85 68.53,23.85 68.55,23.82 68.55,22.38 68.58,22.35 68.58,21.72 68.58,21.71 68.58,21.39 68.47,21.29 64.7,21.29 64.62,21.37 64.62,23.24 67.28,23.24 67.28,23.62 67.03,23.62 67.03,23.24 64.62,23.24 64.62,23.72 64.75,23.86 66.53,23.86 66.58,23.91 66.58,23.92 66.71,24.05 67.16,24.05
5V0 on BOTTOM (solid shape): 58.67,15.88 58.67,14.86 58.55,14.73 55.88,14.73 55.75,14.86 55.75,15.88 55.88,16 58.55,16
5V0 on BOTTOM (solid shape): 66.55,23.62 67.82,23.62 67.94,23.49 67.94,21.84 67.82,21.72 64.9,21.72 64.77,21.84 64.77,23.62 64.9,23.75 66.42,23.75
5V0 on POWER03 (solid shape): outline of 6374 points within 15.62,14.73 96.14,79.63
5V0 on TOP: 50.16,19.05 50.16,17.14 50.04,17.02 48.39,17.02 48.26,17.14 48.26,18.8 48.9,19.43 48.9,20.95 49.28,21.34 50.67,21.34 51.05,20.95 51.05,19.94
5V0 on TOP: 36.07,73.02 36.07,76.3 37.34,77.57 37.34,80.26 36.55,81.05 34.39,81.05 34.04,81.41 31.62,81.41 31.62,74.85 31.11,74.35 31.11,72.9 31.24,72.77 33.78,72.77 34.04,73.02 ; 1 cut-out
5V0 on TOP: 95.76,56.01 95.89,55.88 95.89,53.98 96.27,53.59 96.39,53.59 96.52,53.47 96.52,52.71 96.27,52.45 93.22,52.45 93.09,52.58 93.09,55.25 93.98,56.13 93.98,57.28 94.11,57.4 95.76,57.4 ; 1 cut-out
5V0 on BOTTOM: 35.56,77.34 35.56,73.91 35.43,73.79 32,73.79 31.88,73.91 31.88,77.22 32.13,77.47 35.43,77.47
5V0_MOS on TOP: 48.51,19.56 48.26,19.3 43.56,19.3 43.43,19.43 43.43,22.86 43.56,22.99 48.13,22.99 48.51,22.61
5V0_MOS on TOP: 15.37,80.57 15.62,80.82 15.62,81.66 15.88,81.91 18.16,81.91 18.41,81.66 18.41,79.63 18.29,79.5 15.49,79.5 15.37,79.63 ; 1 cut-out
5V0_MOS on TOP: 82.3,95.88 84.07,95.88 84.2,95.76 84.2,94.23 83.95,93.98 82.3,93.98 82.17,94.11 82.17,95.76
5V0_MOS on TOP: 76.28,88.03 76.91,88.67 76.91,89.81 76.78,89.94 76.53,89.94 76.4,89.81 76.4,89.43 76.15,89.18 75.39,89.18 75.26,89.05 75.26,88.16 75.39,88.03
5V0_MOS on TOP: 19.68,49.07 21.08,49.07 21.21,48.95 21.21,47.42 21.06,47.28 21.06,47.13 21.04,47.11 20.64,47.11 20.45,47.29 20.24,47.29 19.56,47.98 19.56,48.95
5V0_MOS on TOP: 127.64,61.59 129.92,61.59 130.18,61.34 130.18,60.07 129.92,59.82 128.14,59.82 125.98,57.66 124.33,57.66 124.21,57.79 124.21,58.88 124.23,58.9 124.94,58.9
5V0_MOS on BOTTOM: 19.81,48.9 19.94,49.02 19.94,61.34 15.75,65.53 15.75,81.53 13.97,83.31 13.97,85.09 14.22,85.34 15.62,83.95 17.78,83.95 18.41,83.31 18.41,79.88 18.54,79.76 18.54,67.69 24.51,61.72 24.51,28.07 29.72,22.86 44.81,22.86 45.31,22.35 45.31,15.06 46.41,13.97 90.81,13.97 93.73,16.89 99.29,16.89 119.89,37.49 119.89,39.24 125.86,45.21 125.86,54.36 127.13,55.63 127.13,61.34 127.51,61.72 133.99,61.72 135.81,63.55 135.81,86.56 135.8,86.58 135.8,87.11 131.95,90.96 131.95,93.09 131.41,93.64 131.41,95.11 131.57,95.27 133.1,95.27 133.23,95.14 133.23,91.05 136.65,87.63 136.65,60.45 130.81,54.61 130.81,42.29 102.62,14.1 97.28,14.1 94.36,11.18 78.36,11.18 78.23,11.3 69.6,11.3 68.96,11.94 60.83,11.94 59.94,11.05 45.97,11.05 42.06,14.96 42.06,18.67 41.8,18.94 26.78,18.94 19.81,25.91
5V0_SPDIF on TOP (solid shape): 83.69,103.89 83.69,100.58 85.72,98.55 85.72,97.03 85.62,96.93 84.23,96.93 83.95,96.65 82.4,96.65 82.33,96.72 82.33,97.16 85.47,97.16 85.47,97.54 85.22,97.54 85.22,97.16 84.96,97.16 84.96,97.54 84.71,97.54 84.71,97.16 82.33,97.16 82.33,99.44 81.03,100.75 81.03,103.63 81.53,104.14 83.44,104.14
12V0_MOS on TOP: 44.02,81.97 44.45,81.53 44.45,78.35 45.06,77.74 45.06,77.05 44.94,76.93 43.35,76.93 43.23,77.06 43.23,80.09 42.47,80.85 42.47,81.79 42.65,81.97
12V0_MOS on TOP: 110.27,59.44 110.27,57.47 107.95,55.14 106.38,55.14 106.3,55.22 106.3,57.43 106.15,57.58 104.65,57.58 104.52,57.71 104.52,59.41 104.72,59.61 110.1,59.61
12V0_MOS on TOP: 128.27,59.05 130.05,59.05 130.18,58.93 130.18,56.9 130.05,56.77 128.4,56.77 127.51,55.88 124.33,55.88 124.21,56.01 124.21,57.02 124.33,57.15 126.36,57.15
12V0_MOS on POWER03: 130.56,59.05 130.68,58.93 130.68,57.02 130.18,56.52 110.08,56.52 109.3,55.73 108.23,55.73 107.19,56.77 107.19,58.29 107.31,58.42 114.48,58.42 114.68,58.62 114.68,62.48 114.94,62.74 115.82,62.74 119.51,59.05
12V0_PWR on TOP: 20.4,93.9 20.57,93.73 20.57,92.84 23.88,89.53 23.88,85.09 27.05,81.91 27.05,74.68 25.65,74.68 25.4,74.93 22.61,74.93 22.48,75.06 22.48,80.14 21.21,81.41 21.21,83.95 19.94,85.22 19.94,89.03 16.89,92.07 16.89,93.47 17.32,93.9
12V0_PWR on BOTTOM: 39.3,76.78 37.72,78.36 28.45,78.36 26.14,76.05 26.14,75.03 25.65,74.55 24.37,74.55 24.11,74.81 24.11,76.66 27.03,79.58 39.52,79.58 39.89,79.2 41.4,79.2 41.74,78.87 47.41,78.87 47.73,78.55 47.73,77.89 47.72,77.89 47.72,77.44 47.06,76.78
AVDD11_PLL012 on TOP: 65.51,51.33 65.68,51.33 66.17,50.85 66.17,50.6 66.04,50.47 65.91,50.47 65.74,50.65 65.46,50.65 65.28,50.47 65.15,50.47 64.52,51.1 64.52,51.23 64.64,51.36 64.82,51.36 65.05,51.13 65.3,51.13
AVDD11_PLL012 on BOTTOM: 63.75,48.82 63.75,49.53 63.7,49.53 64.9,50.72 64.9,50.85 65.02,50.98 66.17,50.98 66.29,50.85 66.29,49.71 66.17,49.58 64.52,49.58 64.26,49.33 64.26,48.95 64.14,48.82 ; 2 cut-outs
AVDD11_USB3 on TOP: 64.52,48.69 64.52,48.82 64.64,48.95 65.71,48.95 66.23,48.43 66.23,48.25 65.82,47.84 65.74,47.78 65.68,47.7 65.51,47.7
AVDD11_USB3 on BOTTOM: 63.25,47.68 63.63,47.68 63.88,47.93 64.64,47.93 64.77,48.06 64.77,48.31 65.02,48.56 66.17,48.56 66.29,48.44 66.29,48.06 66.17,47.93 65.79,47.93 65.53,47.68 65.53,47.42 65.79,47.17 65.79,46.66 65.66,46.53 65.15,46.53 65.02,46.66 65.02,47.17 64.9,47.29 64.14,47.29 63.88,47.04 63.25,47.04 63.12,47.17 63.12,47.55 ; 2 cut-outs
AVDD33_PLL01 on TOP: 67.06,49.71 67.31,49.71 67.82,49.2 68.07,49.2 68.33,49.45 68.58,49.45 68.71,49.33 68.71,48.82 68.33,48.44 67.94,48.44 66.93,49.45 66.93,49.58
AVDD33_PLL01 on BOTTOM: 67.4,48.41 67.4,49.16 67.03,49.53 67.03,49.98 67.06,50 67.06,49.91 68.71,49.91 68.71,49.91 68.71,49.07 68.58,48.95 68.03,48.95 67.95,48.87 67.95,48.38 67.93,48.35 67.46,48.35
GND on TOP (solid shape): 15.49,31.98 15.49,28.96 15.47,28.93 12.37,28.93 11.94,29.37 11.94,31.67 12.06,31.8 12.78,31.8 13.21,32.23 15.24,32.23
GND on TOP (solid shape): outline of 136 points within 74.4,31.77 110.03,49.49
GND on TOP (solid shape): outline of 250 points within 74.74,16.83 82.74,24.83
GND on TOP (solid shape): outline of 661 points within 86.16,7.62 137.67,93.85
GND on TOP (solid shape): outline of 2212 points within 0.51,7.62 83.19,109.6
GND on TOP (solid shape): outline of 7298 points within 41.66,25.7 127.93,109.6
GND on BOTTOM (solid shape): 61.34,18.8 61.34,16.51 61.09,16.26 54.23,16.26 53.98,16.51 53.98,18.67 54.23,18.92 54.36,18.92 56.26,20.83 57.78,20.83 57.78,21.34 57.4,21.34 57.4,20.83 56.26,20.83 57.15,21.72 58.42,21.72
GND on BOTTOM (solid shape): outline of 19037 points within 0.51,7.51 137.67,109.6
GND on GND02 (solid shape): outline of 37617 points within 0.51,7.62 137.69,109.6
GND on TOP: 48.77,74.93 50.04,74.93 50.16,74.8 50.16,73.15 50.04,73.02 48.77,73.02 48.64,73.15 48.64,74.8
GND on TOP: outline of 213 points within 79.22,55.19 122.38,98.98 ; 18 cut-outs
GND on TOP: 119.79,68.5 119.79,63.4 119.79,60.6 119.34,60.6 118.59,61.35 118.59,63.4 118.57,63.41 113.87,63.41 113.84,63.38 113.84,60.83 113.42,60.41 112.25,60.41 112.12,60.28 112.12,58.69 112.29,58.53 113.71,58.53 114.19,58.06 115.47,58.06 115.54,58.13 115.54,58.91 115.66,59.02 117,59.02 117.09,58.93 117.09,58.23 116.27,57.4 111.76,57.4 111.25,57.91 111.25,62.8 112.02,63.57 112.02,67.62 113.33,68.93 113.77,68.93 113.81,68.91 113.82,68.88 113.82,66.94 113.83,66.93 118.54,66.93 118.7,67.09 118.7,68.19 119.05,68.54 119.74,68.54 ; 3 cut-outs
GND on TOP: 85.98,70.15 89.79,70.15 89.92,70.03 89.92,66.22 89.79,66.09 85.98,66.09 85.85,66.22 85.85,70.03
GND on TOP: 61.22,48.77 61.23,48.74 61.22,48.7 61.19,48.67 61.17,48.67 60.89,48.52 60.87,48.2 60.86,48.1 60.78,48.06 60.38,48.06 60.29,48.15 60.27,48.15 60.23,48.19 60.18,48.25 60.17,48.34 60.18,48.42 60.2,48.45 60.2,48.51 60.33,48.64 60.33,49 60.27,49.05 60.25,49.16 60.34,49.22 60.76,49.22
GND on TOP: 97.24,90.16 100.36,93.28 101.25,93.28 101.38,93.16 101.38,92.19 101.24,92.05 99.85,92.05 97.66,89.86 97.66,89.49 97.49,89.32 97.31,89.32 97.24,89.4
GND on TOP: 72.08,41.78 71.77,42.09 71.77,42.74 71.81,42.82 71.9,42.84 71.95,42.83 72.01,42.8 72.04,42.73 72.61,42.5 72.38,43.07 72.31,43.1 72.28,43.17 72.27,43.2 72.26,43.24 72.28,43.33 72.36,43.37 73.25,43.37 73.38,43.24 73.38,43.24 73.64,42.97 73.64,42.3 73.13,41.78
GND on TOP: 17.53,65.41 23.11,65.41 25.02,67.31 46.74,67.31 48.51,65.53 48.51,64.52 47.62,63.63 47.24,63.63 45.34,65.53 26.04,65.53 23.62,63.12 17.53,63.12 15.62,61.21 15.62,56.77 14.99,56.13 13.72,56.13 12.95,56.9 12.95,58.55 13.34,58.93 13.34,61.21
GND on TOP: outline of 106 points within 48.09,40.28 53.84,47.33
GND on TOP: outline of 85 points within 99.91,31.95 102.82,34.85
GND on TOP: outline of 81 points within 54.17,42.85 59.44,46.53
GND on TOP: 92.41,53.29 92.2,53.09 91.69,53.09 90.55,54.23 89.66,54.23 89.53,54.36 89.53,55.37 89.66,55.5 90.55,55.5 90.68,55.63 92.08,55.63 92.41,55.3
GND on TOP: 114.81,55.63 132.33,55.63 133.99,57.28 133.99,76.07 132.46,77.6 131.06,77.6 130.81,77.85 130.81,81.41 131.19,81.79 134.24,81.79 135.76,80.26 135.76,56.13 132.36,52.73 117.2,52.73 116.08,53.85 111.76,53.85 108.08,50.16 105.41,50.16 104.39,49.15 90.93,49.15 88.65,51.44 82.55,51.44 80.64,53.34 75.18,53.34 74.55,53.98 74.55,54.99 74.68,55.12 81.28,55.12 83.69,52.71 90.04,52.71 91.82,50.93 103.76,50.93 106.55,53.72 109.47,53.72 111.51,55.75 114.68,55.75 ; 2 cut-outs
GND on TOP: 110.27,91.76 108.11,91.76 107.98,91.89 107.98,93.79 108.11,93.92 110.27,93.92 110.4,93.79 110.4,91.89
GND on TOP: 98.76,88.89 100.62,90.75 101.19,90.75 101.38,90.57 101.38,88.04 99.25,85.92 98.81,85.92 98.76,85.97
GND on TOP: 21.21,94.49 24.51,94.49 24.64,94.36 24.64,91.57 24.38,91.31 22.61,91.31 21.08,92.84 21.08,94.36
GND on TOP: 85.09,23.11 70.87,37.34 70.87,41.27 70.99,41.4 72.39,41.4 72.52,41.27 72.52,38.61 85.85,25.27 106.43,25.27 108.33,27.18 113.67,27.18 114.43,27.94 119.76,27.94 121.03,29.21 123.7,29.21 123.83,29.08 123.83,28.7 121.54,28.7 121.54,26.03 121.92,25.65 125.98,25.65 126.62,26.29 128.91,26.29 130.05,25.15 130.05,21.21 129.92,21.08 129.54,21.08 129.41,21.21 129.41,23.37 128.52,24.26 120.02,24.26 119.76,24.51 112.9,24.51 111.51,23.11
GND on TOP: 120.65,55.75 120.4,56.01 120.4,63.75 121.03,64.39 124.71,64.39 125.22,64.9 125.22,72.64 125.48,72.9 131.52,72.9 131.72,72.69 131.72,68.55 132.64,68.55 132.64,62.59 132.03,61.98 127.38,61.98 124.71,59.31 123.83,59.31 123.7,59.18 123.7,55.88 123.57,55.75
GND on TOP: 90.42,45.34 86.74,49.02 81.28,49.02 79.76,50.55 77.47,50.55 76.71,51.31 76.71,52.2 80.01,52.2 80.01,52.58 76.71,52.58 76.71,52.83 76.83,52.96 80.52,52.96 82.55,50.93 88.39,50.93 91.06,48.26 104.52,48.26 105.79,49.53 105.82,49.53 106.12,49.83 108.51,49.83 110.13,51.46 111.43,51.46 111.63,51.26 111.63,46.61 111.51,46.48 111.12,46.48 110.87,46.74 107.06,46.74 105.66,45.34
GND on TOP: 34.62,50.91 31.95,50.91 31.7,51.16 31.7,54.01 31.98,54.29 36.29,54.29 36.42,54.15 36.42,53.7 36.4,53.7 36.15,53.44 36.15,52.05 36.07,51.97 36.07,50.34 36.14,50.27 40.34,50.27 41.23,51.16 43.99,51.16 46.2,48.96 46.2,48.73 46.11,48.65 43.45,48.65 40.37,45.57 39.96,45.57
GND on TOP: 114.16,90.23 114.16,92.19 114.18,92.22 115.1,92.22 115.25,92.06 115.35,92.06 115.38,92.05 115.4,92.01 115.4,89.16 115.38,89.12 115.35,89.1 113.76,89.1 113.65,89.22 113.65,89.73 ; 1 cut-out
GND on TOP: 75.13,89.43 76.02,89.43 76.2,89.61 76.2,91.82 76.02,91.99 75.59,91.99 75.31,91.72 74.8,91.72 74.75,91.66 74.75,90.83 75.01,90.57 75.01,89.56 ; 1 cut-out
GND on TOP: 96.52,55.5 97.92,55.5 98.04,55.37 98.04,53.98 97.92,53.85 96.52,53.85 96.39,53.98 96.39,55.37
GND on TOP: 57.54,51.58 57.58,51.59 57.61,51.58 57.94,51.25 57.94,49.98 57.87,49.89 57.76,49.91 57.71,49.96 57.48,49.96 57.37,49.85 57.36,49.83 57.32,49.79 57.28,49.75 57.26,49.74 57.22,49.71 56.95,49.71 56.9,49.76 56.9,51.14 56.94,51.22 57.04,51.23 57.36,51.25 57.51,51.53 57.51,51.55
GND on TOP: 68.2,64.52 68.07,64.64 68.07,66.93 68.45,67.31 68.45,77.85 66.93,79.38 66.93,79.63 61.85,84.71 61.85,91.82 61.98,91.95 63.37,91.95 63.5,91.82 63.5,90.68 63.63,90.55 64.01,90.55 64.01,89.79 64.26,89.53 66.17,89.53 66.55,89.15 66.55,88.27 65.79,87.5 65.79,84.84 65.91,84.71 66.42,84.71 66.55,84.58 66.55,84.07 66.17,83.69 66.17,81.66 66.42,81.41 67.44,81.41 67.56,81.28 67.56,80.52 67.69,80.39 70.13,80.39 70.1,80.42 70.1,81.31 70.26,81.46 71.15,81.46 71.4,81.71 71.4,83.79 70.97,84.23 70.79,84.23 70.66,84.35 70.66,84.81 70.74,84.89 71.17,84.89 71.4,85.12 71.4,88.85 71.04,89.2 71.04,89.41 71.2,89.56 72.9,89.56 73.05,89.41 73.05,86.59 72.14,85.67 72.14,80.67 71.5,80.04 71.5,66.29 69.72,64.52 ; 3 cut-outs
GND on BOTTOM: 82.55,65.79 82.93,65.41 83.69,65.41 83.82,65.28 83.82,64.39 83.69,64.26 82.17,64.26 81.79,64.64 81.79,65.66 81.92,65.79
GND on BOTTOM: 41.22,42.42 41.05,42.6 40.01,42.6 40.01,44.12 39.85,44.12 39.96,44.23 39.96,44.94 39.96,44.94 39.96,45.83 40.08,45.96 40.08,47.48 40.21,47.61 41.35,47.61 41.48,47.73 41.48,49.53 41.48,49.53 41.48,49.89 41.27,50.09 39.5,50.09 39.34,50.25 39.34,52.6 39.46,52.72 39.42,52.76 39.42,53.26 39.71,53.55 39.71,54.39 39.19,54.91 39.19,57.27 39.32,57.41 39.84,57.41 40.05,57.19 40.05,56.38 40.35,56.08 41.57,56.08 41.98,56.49 41.98,57.57 41.98,57.57 41.98,57.78 41.98,57.78 41.98,59.2 42.21,59.42 43.13,59.42 43.77,58.78 43.77,57.77 42.17,56.17 41.86,55.77 42.29,55.51 42.3,55.52 42.88,55.52 42.89,55.51 42.99,55.5 43.09,55.51 43.1,55.52 43.68,55.52 43.69,55.51 43.79,55.5 43.89,55.51 43.9,55.52 43.99,55.52 44.06,55.44 44.06,55.15 44.68,54.53 44.7,54.53 44.83,54.41 45.54,54.41 45.72,54.58 46.08,54.58 46.23,54.43 46.23,52.5 49.12,49.61 49.12,48.48 47.2,46.56 43.1,46.56 43.1,43.99 41.53,42.42 ; 10 cut-outs
GND on POWER03: outline of 109 points within 0.51,7.62 137.69,109.6 ; 23 cut-outs
VCC_SCI on TOP: 107.35,19.05 108.84,19.05 109.35,18.54 109.35,13.8 107.31,11.76 107.31,9.14 107.19,9.02 104.27,9.02 104.01,9.27 104.01,11.83 106.74,14.56 106.74,18.45 ; 7 cut-outs
VDD_AUDIO on TOP: 74.49,91.56 74.49,90.7 74.74,90.45 74.74,88.16 74.61,88.03 73.47,88.03 73.34,88.16 73.34,91.55 73.46,91.66 74.38,91.66 ; 1 cut-out
HDMI_TX_1V1 on BOTTOM: 63.75,57.45 63.63,57.58 63.63,58.22 63.5,58.34 62.48,58.34 62.36,58.47 62.36,59.36 61.98,59.74 61.98,60.38 62.36,60.38 62.48,60.25 62.48,59.87 62.61,59.74 63.75,59.74 63.88,59.61 63.88,59.23 64.01,59.11 64.39,59.11 64.52,58.98 64.52,58.47 64.77,58.22 65.41,58.22 65.53,58.09 65.53,57.58 65.41,57.45 ; 1 cut-out
HDMI_TX_3V3 on TOP: 64.5,60.87 64.14,60.5 63.12,60.5 62.99,60.63 62.99,60.86 63,60.88 63.01,60.89 63.03,60.92 63.05,60.95 63.5,61.39 63.63,61.39 63.75,61.26 63.84,61.26 63.85,61.26 63.98,61.23 64.1,61.26 64.14,61.26 64.26,61.39 64.48,61.39 64.5,61.39 64.52,61.37 64.56,61.32 64.62,61.28 64.64,61.26 64.64,61.23 64.64,61.04 64.64,61.02 64.62,61 64.55,60.94
HDMI_TX_3V3 on BOTTOM: 63.63,60.2 63.63,60.76 63.37,61.01 63.37,61.26 63.63,61.52 65.28,61.52 65.28,60.88 65.15,60.76 65.15,60.2 ; 2 cut-outs
USB01_1V1 on BOTTOM: 57.84,59.03 58.88,59.03 59.03,58.88 59.03,58.09 59.11,58.01 60.3,58.01 60.35,57.96 60.35,57.53 60.25,57.43 57.84,57.43 57.78,57.48 57.78,58.98
USB01_VBUS on TOP: 9.27,72.52 9.27,71.5 8,70.23 8,69.22 8.64,68.58 10.54,68.58 10.79,68.33 13.21,68.33 13.34,68.45 13.34,68.96 13.65,69.28 15.05,69.28 15.75,69.98 15.75,73.15 18.03,75.44 18.03,77.47 17.53,77.98 15.37,77.98 15.24,77.85 15.24,76.96 14.61,76.33 11.68,76.33 10.54,75.18 10.54,73.79
USB01_VBUS on TOP: 8.51,92.46 10.79,92.46 11.3,92.96 12.57,92.96 12.83,92.71 12.83,91.95 13.21,91.57 13.21,90.17 13.08,90.04 11.68,90.04 10.92,90.8 8.38,90.8 8.26,90.93 8.26,92.2 ; 2 cut-outs
USB01_VBUS on POWER03: 13.21,92.46 13.21,87.18 13.52,86.87 13.52,86.86 13.72,86.67 13.72,69.47 13.24,68.99 9.01,68.99 9,69 8.78,69 8.49,69.29 8.49,69.83 10.54,71.88 10.54,79.75 10.54,79.75 10.54,85.34 10.41,85.47 10.41,90.55 10.03,90.93 8.89,90.93 8.38,91.44 8.38,92.84 8.64,93.09 12.57,93.09
VDAC_3V3 on BOTTOM: 69.09,60.63 72.26,60.63 72.39,60.76 72.39,61.06 72.49,61.16 73.23,61.16 73.3,61.09 73.3,60.15 73.15,59.99 69.09,59.99 68.96,60.12 68.96,60.5
$4N758 on TOP: 20.32,95.38 20.19,95.25 15.49,95.25 15.37,95.38 15.37,98.42 15.24,98.55 15.24,100.96 15.62,101.35 19.18,101.35 19.81,100.71 19.81,97.92 20.32,97.41
$4N759 on TOP: 23.88,98.17 23.88,95.88 23.75,95.76 21.46,95.76 21.34,95.88 21.34,103.3 20.35,104.29 15.11,104.29 13.82,103 13.82,100.71 13.26,100.15 11.23,100.15 10.03,101.35 10.03,107.44 10.35,107.76 22.92,107.76 24.26,106.43 24.26,98.55
$4N759 on BOTTOM: 24.13,107.7 24.38,107.44 24.38,97.66 24,97.28 21.46,97.28 21.08,97.66 21.08,100.33 19.3,102.11 15.75,102.11 13.34,99.69 10.92,99.69 10.79,99.82 10.79,107.31 11.18,107.7
